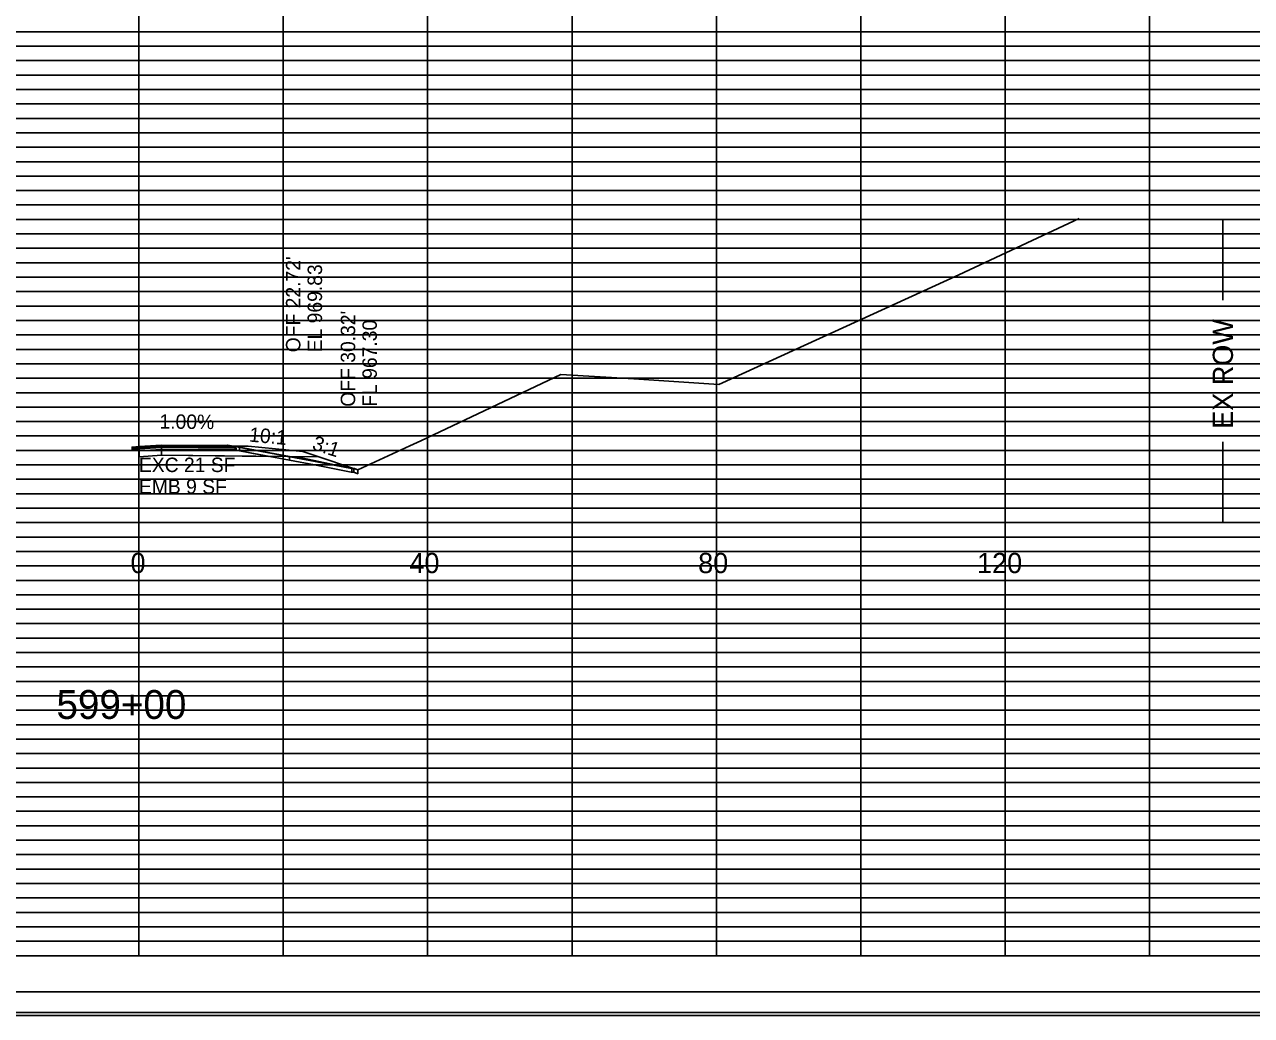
# Model space of a CAD drawing. Extents: x 2313580 to 2322968, y 282099 to 303247.
# Drawn here: x 2316394.2 to 2316564.2, y 287579.4 to 287716.7 of the extents above; entities that cross this region are included whole.
import ezdxf

# ---------------------------------------------------------------- set-up
doc = ezdxf.new("R2010")
doc.units = 0
for name, color, linetype in [('DESIGN - DRAINAGE - Text', 7, 'Continuous'), ('DESIGN - EARTHWORK - Excavation Limit Lines', 7, 'Continuous'), ('DESIGN - EARTHWORK - Shapes', 7, 'Continuous'), ('DESIGN - SCRATCH - User 5', 7, 'Continuous'), ('DESIGN - SHEET - Light Grid', 7, 'Continuous'), ('DESIGN - SHEET - Linework', 7, 'Continuous'), ('DESIGN - SHEET - Plot Shape', 7, 'Continuous'), ('DESIGN - TYPICAL - Finished Grade and Subgrade', 7, 'Continuous'), ('DESIGN - TYPICAL - Finished Grade Slopes Text', 7, 'Continuous'), ('DESIGN - TYPICAL - Text', 7, 'Continuous'), ('Scratch Level', 7, 'Continuous'), ('SURVEY - GROUND - Top of Ground', 7, 'Continuous'), ('SURVEY - PROPERTY - ROW Lines Text', 7, 'Continuous')]:
    doc.layers.add(name, color=color, linetype=linetype)

msp = doc.modelspace()

# ---------------------------------------------------------------- linework, layer by layer
at = {"layer": 'DESIGN - EARTHWORK - Shapes'}
for points in [[(2316428.09, 287656.84), (2316424.02, 287657.61), (2316424.02, 287658.11), (2316422.36, 287658.42), (2316417.38, 287658.36), (2316410.08, 287658.2), (2316410.08, 287657.88), (2316410.14, 287657.88), (2316410.14, 287657.63), (2316410.14, 287656.8), (2316413.23, 287656.99)], [(2316430.95, 287656.81), (2316434.51, 287656.15), (2316439.53, 287655.15), (2316439.85, 287655.16), (2316439.54, 287655.26), (2316434.99, 287656.77)]]:
    msp.add_lwpolyline(points, close=True, dxfattribs=at)
at = {"layer": 'DESIGN - SCRATCH - User 5'}
for points in [[(2316430.95, 287656.81), (2316424.02, 287658.11), (2316424.02, 287657.61), (2316430.95, 287656.31)], [(2316430.95, 287656.81), (2316424.02, 287658.11), (2316424.02, 287657.61), (2316430.95, 287656.31)], [(2316439.59, 287655.15), (2316439.53, 287655.15), (2316434.51, 287656.15), (2316430.95, 287656.81), (2316430.95, 287656.31), (2316434.41, 287655.66), (2316439.49, 287654.64), (2316439.59, 287654.65)], [(2316439.85, 287655.16), (2316439.53, 287655.15), (2316434.51, 287656.15), (2316430.95, 287656.81), (2316430.95, 287656.31), (2316434.41, 287655.66), (2316439.49, 287654.64), (2316439.85, 287654.66), (2316439.85, 287654.66)], [(2316439.59, 287654.65), (2316439.85, 287654.66), (2316440.4, 287654.43), (2316440.4, 287654.97), (2316439.93, 287655.16), (2316439.59, 287655.15)], [(2316439.85, 287654.66), (2316440.4, 287654.43), (2316440.4, 287654.97), (2316439.93, 287655.16), (2316439.85, 287655.16)]]:
    msp.add_lwpolyline(points, close=True, dxfattribs=at)
at = {"layer": 'DESIGN - SHEET - Light Grid'}
for p, q in [((2316250.08, 287715.67), (2316410.08, 287715.67)), ((2316410.08, 287715.67), (2316570.08, 287715.67)), ((2316250.08, 287713.67), (2316410.08, 287713.67)), ((2316410.08, 287713.67), (2316570.08, 287713.67)), ((2316250.08, 287711.67), (2316410.08, 287711.67)), ((2316410.08, 287711.67), (2316570.08, 287711.67)), ((2316250.08, 287709.67), (2316410.08, 287709.67)), ((2316410.08, 287709.67), (2316570.08, 287709.67)), ((2316250.08, 287705.67), (2316410.08, 287705.67)), ((2316410.08, 287705.67), (2316570.08, 287705.67)), ((2316250.08, 287703.67), (2316410.08, 287703.67)), ((2316410.08, 287703.67), (2316570.08, 287703.67)), ((2316250.08, 287701.67), (2316410.08, 287701.67)), ((2316410.08, 287701.67), (2316570.08, 287701.67)), ((2316250.08, 287699.67), (2316410.08, 287699.67)), ((2316410.08, 287699.67), (2316570.08, 287699.67)), ((2316250.08, 287697.67), (2316410.08, 287697.67)), ((2316410.08, 287697.67), (2316570.08, 287697.67)), ((2316250.08, 287695.67), (2316410.08, 287695.67)), ((2316410.08, 287695.67), (2316570.08, 287695.67)), ((2316250.08, 287693.67), (2316410.08, 287693.67)), ((2316410.08, 287693.67), (2316570.08, 287693.67)), ((2316250.08, 287691.67), (2316410.08, 287691.67)), ((2316410.08, 287691.67), (2316570.08, 287691.67)), ((2316250.08, 287689.67), (2316410.08, 287689.67)), ((2316410.08, 287689.67), (2316570.08, 287689.67)), ((2316250.08, 287685.67), (2316410.08, 287685.67)), ((2316410.08, 287685.67), (2316570.08, 287685.67)), ((2316250.08, 287683.67), (2316410.08, 287683.67)), ((2316410.08, 287683.67), (2316570.08, 287683.67)), ((2316250.08, 287681.67), (2316410.08, 287681.67)), ((2316410.08, 287681.67), (2316570.08, 287681.67)), ((2316250.08, 287679.67), (2316410.08, 287679.67)), ((2316410.08, 287679.67), (2316570.08, 287679.67)), ((2316250.08, 287677.67), (2316410.08, 287677.67)), ((2316410.08, 287677.67), (2316570.08, 287677.67)), ((2316250.08, 287675.67), (2316410.08, 287675.67)), ((2316410.08, 287675.67), (2316570.08, 287675.67)), ((2316250.08, 287673.67), (2316410.08, 287673.67)), ((2316410.08, 287673.67), (2316570.08, 287673.67)), ((2316250.08, 287671.67), (2316410.08, 287671.67)), ((2316410.08, 287671.67), (2316570.08, 287671.67)), ((2316250.08, 287669.67), (2316410.08, 287669.67)), ((2316410.08, 287669.67), (2316570.08, 287669.67)), ((2316250.08, 287665.67), (2316410.08, 287665.67)), ((2316410.08, 287665.67), (2316570.08, 287665.67)), ((2316250.08, 287663.67), (2316410.08, 287663.67)), ((2316410.08, 287663.67), (2316570.08, 287663.67)), ((2316250.08, 287661.67), (2316410.08, 287661.67)), ((2316410.08, 287661.67), (2316570.08, 287661.67)), ((2316250.08, 287659.67), (2316410.08, 287659.67)), ((2316410.08, 287659.67), (2316570.08, 287659.67)), ((2316250.08, 287657.67), (2316410.08, 287657.67)), ((2316410.08, 287657.67), (2316570.08, 287657.67)), ((2316250.08, 287655.67), (2316410.08, 287655.67)), ((2316410.08, 287655.67), (2316570.08, 287655.67)), ((2316250.08, 287653.67), (2316410.08, 287653.67)), ((2316410.08, 287653.67), (2316570.08, 287653.67)), ((2316250.08, 287651.67), (2316410.08, 287651.67)), ((2316410.08, 287651.67), (2316570.08, 287651.67)), ((2316250.08, 287649.67), (2316410.08, 287649.67)), ((2316410.08, 287649.67), (2316570.08, 287649.67)), ((2316250.08, 287645.67), (2316410.08, 287645.67)), ((2316410.08, 287645.67), (2316570.08, 287645.67)), ((2316250.08, 287643.67), (2316410.08, 287643.67)), ((2316410.08, 287643.67), (2316570.08, 287643.67)), ((2316250.08, 287641.67), (2316410.08, 287641.67)), ((2316410.08, 287641.67), (2316570.08, 287641.67)), ((2316250.08, 287639.67), (2316410.08, 287639.67)), ((2316410.08, 287639.67), (2316570.08, 287639.67)), ((2316250.08, 287637.67), (2316410.08, 287637.67)), ((2316410.08, 287637.67), (2316570.08, 287637.67)), ((2316250.08, 287635.67), (2316410.08, 287635.67)), ((2316410.08, 287635.67), (2316570.08, 287635.67)), ((2316250.08, 287633.67), (2316410.08, 287633.67)), ((2316410.08, 287633.67), (2316570.08, 287633.67)), ((2316250.08, 287631.67), (2316410.08, 287631.67)), ((2316410.08, 287631.67), (2316570.08, 287631.67)), ((2316250.08, 287629.67), (2316410.08, 287629.67)), ((2316410.08, 287629.67), (2316570.08, 287629.67)), ((2316250.08, 287625.67), (2316410.08, 287625.67)), ((2316410.08, 287625.67), (2316570.08, 287625.67)), ((2316250.08, 287623.67), (2316410.08, 287623.67)), ((2316410.08, 287623.67), (2316570.08, 287623.67)), ((2316250.08, 287621.67), (2316410.08, 287621.67)), ((2316410.08, 287621.67), (2316570.08, 287621.67)), ((2316250.08, 287619.67), (2316410.08, 287619.67)), ((2316410.08, 287619.67), (2316570.08, 287619.67)), ((2316250.08, 287617.67), (2316410.08, 287617.67)), ((2316410.08, 287617.67), (2316570.08, 287617.67)), ((2316250.08, 287615.67), (2316410.08, 287615.67)), ((2316410.08, 287615.67), (2316570.08, 287615.67)), ((2316250.08, 287613.67), (2316410.08, 287613.67)), ((2316410.08, 287613.67), (2316570.08, 287613.67)), ((2316250.08, 287611.67), (2316410.08, 287611.67)), ((2316410.08, 287611.67), (2316570.08, 287611.67)), ((2316250.08, 287609.67), (2316410.08, 287609.67)), ((2316410.08, 287609.67), (2316570.08, 287609.67)), ((2316250.08, 287605.67), (2316410.08, 287605.67)), ((2316410.08, 287605.67), (2316570.08, 287605.67)), ((2316250.08, 287603.67), (2316410.08, 287603.67)), ((2316410.08, 287603.67), (2316570.08, 287603.67)), ((2316250.08, 287601.67), (2316410.08, 287601.67)), ((2316410.08, 287601.67), (2316570.08, 287601.67)), ((2316250.08, 287599.67), (2316410.08, 287599.67)), ((2316410.08, 287599.67), (2316570.08, 287599.67)), ((2316250.08, 287597.67), (2316410.08, 287597.67)), ((2316410.08, 287597.67), (2316570.08, 287597.67)), ((2316250.08, 287595.67), (2316410.08, 287595.67)), ((2316410.08, 287595.67), (2316570.08, 287595.67)), ((2316250.08, 287593.67), (2316410.08, 287593.67)), ((2316410.08, 287593.67), (2316570.08, 287593.67)), ((2316250.08, 287591.67), (2316410.08, 287591.67)), ((2316410.08, 287591.67), (2316570.08, 287591.67)), ((2316250.08, 287589.67), (2316410.08, 287589.67)), ((2316410.08, 287589.67), (2316570.08, 287589.67))]:
    msp.add_line(p, q, dxfattribs=at)
at = {"layer": 'DESIGN - SHEET - Linework'}
for p, q in [((2316410.08, 287587.67), (2316410.08, 288007.67)), ((2316430.08, 287587.67), (2316430.08, 288007.67)), ((2316450.08, 287587.67), (2316450.08, 288007.67)), ((2316470.08, 287587.67), (2316470.08, 288007.67)), ((2316490.08, 287587.67), (2316490.08, 288007.67)), ((2316510.08, 287587.67), (2316510.08, 288007.67)), ((2316530.08, 287587.67), (2316530.08, 288007.67)), ((2316550.08, 287587.67), (2316550.08, 288007.67)), ((2316090.08, 287707.67), (2316730.08, 287707.67)), ((2316090.08, 287687.67), (2316730.08, 287687.67)), ((2316090.08, 287667.67), (2316730.08, 287667.67)), ((2316090.08, 287647.67), (2316730.08, 287647.67)), ((2316090.08, 287627.67), (2316730.08, 287627.67)), ((2316090.08, 287607.67), (2316730.08, 287607.67)), ((2316053.62, 287579.39), (2316734.42, 287579.39))]:
    msp.add_line(p, q, dxfattribs=at)
msp.add_lwpolyline([(2316090.08, 288007.67), (2316090.08, 287587.67), (2316730.08, 287587.67), (2316730.08, 288007.67), (2316090.08, 288007.67)], dxfattribs=at)
at = {"layer": 'DESIGN - SHEET - Plot Shape'}
for points in [[(2316054.02, 288015.55), (2316734.02, 288015.55), (2316734.02, 287579.79), (2316054.02, 287579.79)], [(2316073.08, 288007.67), (2316730.08, 288007.67), (2316730.08, 287582.67), (2316073.08, 287582.67)]]:
    msp.add_lwpolyline(points, close=True, dxfattribs=at)
at = {"layer": 'DESIGN - TYPICAL - Finished Grade and Subgrade'}
msp.add_lwpolyline([(2316409.14, 287658.14), (2316409.26, 287658.14), (2316410.14, 287658.2), (2316412.79, 287658.36), (2316413.23, 287658.38), (2316422.02, 287658.29), (2316423.23, 287658.28), (2316424.99, 287658.26), (2316425.23, 287658.26), (2316432.8, 287657.51), (2316434.88, 287656.81), (2316439.54, 287655.26), (2316440.4, 287654.97)], dxfattribs=at)
for points in [[(2316410.14, 287658.2), (2316409.14, 287658.14), (2316409.14, 287658.04), (2316410.14, 287658.09)], [(2316410.14, 287658.09), (2316410.14, 287657.88), (2316409.14, 287657.83), (2316409.14, 287658.04)], [(2316410.14, 287658.2), (2316413.23, 287658.38), (2316413.23, 287658.28), (2316410.14, 287658.09)], [(2316410.14, 287658.09), (2316413.23, 287658.28), (2316413.23, 287658.07), (2316410.14, 287657.88)], [(2316410.14, 287657.88), (2316413.23, 287658.07), (2316413.23, 287657.82), (2316410.14, 287657.63)], [(2316410.14, 287657.63), (2316413.23, 287657.82), (2316413.23, 287656.99), (2316410.14, 287656.8)], [(2316413.23, 287658.38), (2316423.23, 287658.28), (2316423.23, 287658.18), (2316413.23, 287658.28)], [(2316413.23, 287658.28), (2316423.33, 287658.18), (2316423.33, 287657.98), (2316413.23, 287658.07)], [(2316413.23, 287657.82), (2316423.54, 287657.73), (2316423.54, 287657.98), (2316423.33, 287657.98), (2316423.33, 287658.18), (2316423.23, 287658.18), (2316423.23, 287658.28), (2316425.23, 287658.26), (2316432.8, 287657.51), (2316434.99, 287656.77), (2316413.23, 287656.99)], [(2316413.23, 287658.07), (2316423.54, 287657.98), (2316423.54, 287657.73), (2316413.23, 287657.82)]]:
    msp.add_lwpolyline(points, close=True, dxfattribs=at)
at = {"layer": 'Scratch Level'}
for points in [[(2316428.09, 287656.84), (2316424.02, 287657.61), (2316424.02, 287658.11), (2316422.36, 287658.42), (2316417.38, 287658.36), (2316410.08, 287658.2), (2316410.08, 287657.88), (2316410.14, 287657.88), (2316410.14, 287657.63), (2316410.14, 287656.8), (2316413.23, 287656.99)], [(2316430.95, 287656.81), (2316434.51, 287656.15), (2316439.53, 287655.15), (2316439.59, 287655.15), (2316431.95, 287656.8)]]:
    msp.add_lwpolyline(points, close=True, dxfattribs=at)
at = {"layer": 'SURVEY - GROUND - Top of Ground'}
msp.add_lwpolyline([(2316410.08, 287658.2), (2316417.38, 287658.36), (2316422.36, 287658.42), (2316434.51, 287656.15), (2316439.53, 287655.15), (2316439.93, 287655.16), (2316440.4, 287654.97), (2316440.41, 287654.98), (2316440.42, 287654.98), (2316447.61, 287658.29), (2316449.14, 287659), (2316468.51, 287668.18), (2316478.63, 287667.6), (2316490.4, 287666.78), (2316523.66, 287681.99), (2316540.31, 287689.79)], dxfattribs=at)
at = {"layer": 'SURVEY - PROPERTY - ROW Lines Text'}
for p, q in [((2316560.23, 287689.67), (2316560.23, 287678.47)), ((2316560.23, 287647.67), (2316560.23, 287658.87))]:
    msp.add_line(p, q, dxfattribs=at)

# ---------------------------------------------------------------- texts
at = {"layer": 'DESIGN - DRAINAGE - Text'}
for s, p in [("OFF 22.72'", (2316432.45, 287671.26)), ('EL 969.83', (2316435.45, 287671.26)), ("OFF 30.32'", (2316440.04, 287663.72)), ('FL 967.30', (2316443.04, 287663.72))]:
    msp.add_text(s, height=2, rotation=90, dxfattribs=at).set_placement(p)
at = {"layer": 'DESIGN - EARTHWORK - Excavation Limit Lines'}
for s, p in [('EXC 21 SF', (2316410.08, 287654.67)), ('EMB 9 SF', (2316410.08, 287651.67))]:
    msp.add_text(s, height=2, dxfattribs=at).set_placement(p)
at = {"layer": 'DESIGN - TYPICAL - Finished Grade Slopes Text'}
for s, rotation, p in [('1.00%', 359.4291, (2316412.92, 287660.69)), ('10:1', 354.704, (2316425.29, 287658.9)), ('3:1', 341.8879, (2316433.96, 287657.85))]:
    msp.add_text(s, height=2, rotation=rotation, dxfattribs=at).set_placement(p)
at = {"layer": 'DESIGN - TYPICAL - Text'}
for s, height, p in [('0', 2.8, (2316408.92, 287640.67)), ('40', 2.8, (2316447.55, 287640.67)), ('80', 2.8, (2316487.55, 287640.67)), ('120', 2.8, (2316526.19, 287640.67)), ('599+00', 4, (2316398.66, 287620.47))]:
    msp.add_text(s, height=height, dxfattribs=at).set_placement(p)
at = {"layer": 'SURVEY - PROPERTY - ROW Lines Text'}
msp.add_text('EX ROW', height=2.8, rotation=90, dxfattribs=at).set_placement((2316561.63, 287660.67))

doc.saveas('drawing.dxf')
